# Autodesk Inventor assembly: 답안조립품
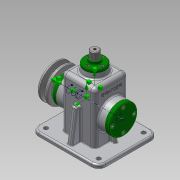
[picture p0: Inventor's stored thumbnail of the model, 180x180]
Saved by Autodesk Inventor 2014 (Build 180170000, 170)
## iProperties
Created: 2016-08
Part Number: 답안조립품
Document SubType Name: Assembly
Designer: user
Author: user
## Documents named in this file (19)
- C:\Users\user\Desktop\460820V1006\답안조립품.iam
- C:\Users\user\Desktop\460820V1006\본체.ipt
- C:\Users\user\Desktop\460820V1006\V-벨트풀리.ipt
- C:\Users\user\Desktop\460820V1006\고정핀.ipt
- C:\Users\user\Desktop\460820V1006\뒤커버.ipt
- C:\Users\user\Desktop\460820V1006\링크.ipt
- C:\Users\user\Desktop\460820V1006\멈춤링 6 x 5.ipt
- C:\Users\user\Desktop\460820V1006\멈춤링 15 x 1.ipt
- C:\Users\user\Desktop\460820V1006\베어링 15 x 35 x 11.ipt
- C:\Users\user\Desktop\460820V1006\볼트 M3 x 8.ipt
- C:\Users\user\Desktop\460820V1006\볼트 M4 x 10.ipt
- C:\Users\user\Desktop\460820V1006\볼트 M6 x 12.ipt
- C:\Users\user\Desktop\460820V1006\상부부시.ipt
- C:\Users\user\Desktop\460820V1006\슬라이드바.ipt
- C:\Users\user\Desktop\460820V1006\앞커버.ipt
- C:\Users\user\Desktop\460820V1006\오일실 15 25 7.ipt
- C:\Users\user\Desktop\460820V1006\와셔.ipt
- C:\Users\user\Desktop\460820V1006\키 5 x 5 x 14.ipt
- C:\Users\user\Desktop\460820V1006\편심축.ipt
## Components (15 placed, 5 different names)
1. V-벨트풀리:1 — 각도:1
2. 고정핀:1 — 강체:8, 강체:9, 강체:10
3. ISO 4018 M6 x 12:1 — 강체:2
4. ISO 4762 M3 x 8:1 — 강체:7
5. ISO 4762 M3 x 8:2
6. ISO 4762 M3 x 8:3
7. ISO 4762 M3 x 8:4
8. ISO 4762 M4 x 10:1 — 강체:6
9. ISO 4762 M4 x 10:3
10. ISO 4762 M4 x 10:4
11. ISO 4762 M4 x 10:5
12. ISO 4762 M4 x 10:2 — 강체:5
13. ISO 4762 M4 x 10:6
14. ISO 4762 M4 x 10:7
15. ISO 4762 M4 x 10:8
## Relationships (8: WeldJoint 7, Angle 1)
- 강체:2 [WeldJoint]: ISO 4018 M6 x 12:1
- 강체:5 [WeldJoint]: ISO 4762 M4 x 10:2
- 강체:6 [WeldJoint]: ISO 4762 M4 x 10:1
- 강체:7 [WeldJoint]: ISO 4762 M3 x 8:1
- 강체:8 [WeldJoint]: 고정핀:1
- 강체:9 [WeldJoint]: 고정핀:1
- 각도:1 [Angle]: V-벨트풀리:1
- 강체:10 [WeldJoint]: 고정핀:1
